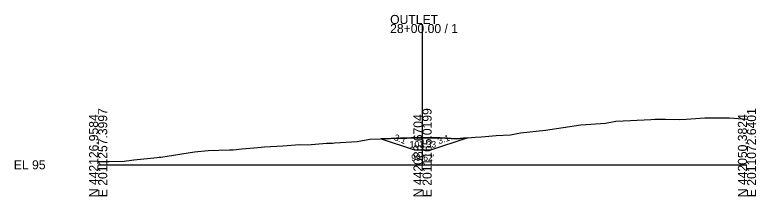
# Model space of a CAD drawing. Extents: x -26 to 1203, y -15 to 9526.
# Drawn here: x 974.3 to 1202.8, y 7990.3 to 8046.3 of the extents above; entities that cross this region are included whole.
import ezdxf

# ---------------------------------------------------------------- set-up
doc = ezdxf.new("R2010")
doc.units = 0
for name, color, linetype in [('Default', 7, 'Continuous'), ('Exist Cross Section Cell', 7, 'Continuous'), ('Exist XS Center Line Elevation Label', 7, 'Continuous'), ('Exist XS Ground Line', 7, 'Continuous'), ('Prop XS DDE', 7, 'Continuous'), ('Prop XS DDE Earthwork Shape', 7, 'Continuous'), ('Prop XS DDE Elevations', 7, 'Continuous'), ('Prop XS DDE Slope Text', 7, 'Continuous')]:
    doc.layers.add(name, color=color, linetype=linetype)

msp = doc.modelspace()

# ---------------------------------------------------------------- linework, layer by layer
at = {"layer": 'Exist Cross Section Cell'}
for p, q in [((1100, 8000), (1100, 8043.49)), ((1000, 8000), (1100, 8000)), ((1100, 8000), (1200, 8000))]:
    msp.add_line(p, q, dxfattribs=at)
at = {"layer": 'Exist XS Ground Line'}
msp.add_lwpolyline([(1000, 8001.01), (1003.34, 8001.04), (1008.01, 8001.1), (1010.99, 8001.53), (1018.17, 8002.27), (1018.83, 8002.35), (1019.3, 8002.41), (1029.66, 8003.97), (1033.95, 8004.44), (1040.48, 8004.66), (1041.6, 8004.65), (1044.29, 8004.95), (1049.25, 8005.39), (1051.31, 8005.59), (1056.91, 8005.9), (1062.13, 8006.23), (1064.56, 8006.18), (1070.41, 8006.71), (1072.21, 8006.73), (1072.96, 8006.77), (1079.87, 8007.24), (1083.78, 8007.91), (1093.25, 8008.27), (1094.61, 8008.28), (1095.17, 8008.26), (1096.53, 8008.36), (1100, 8008.33), (1105.43, 8008.29), (1110.48, 8008.07), (1116.26, 8008.58), (1118.13, 8008.61), (1122.65, 8009.09), (1127.08, 8009.31), (1130.23, 8009.89), (1137.91, 8010.69), (1148.76, 8012.37), (1156.4, 8012.91), (1159.56, 8013.45), (1164.05, 8013.69), (1170.38, 8014), (1171.7, 8014.09), (1174.88, 8014.09), (1179.35, 8013.96), (1181.21, 8014.11), (1187.01, 8014.49), (1192.03, 8014.46), (1194.66, 8014.5), (1200, 8014.06)], dxfattribs=at)
at = {"layer": 'Prop XS DDE'}
for p, q in [((1087.23, 8008.04), (1097.5, 8004.62)), ((1102.5, 8004.62), (1113.71, 8008.36)), ((1097.5, 8004.62), (1102.5, 8004.62))]:
    msp.add_line(p, q, dxfattribs=at)
at = {"layer": 'Prop XS DDE Earthwork Shape'}
msp.add_lwpolyline([(1087.23, 8008.04), (1097.5, 8004.62), (1102.5, 8004.62), (1113.71, 8008.36), (1110.48, 8008.07), (1105.43, 8008.29), (1100, 8008.33), (1096.53, 8008.36), (1095.17, 8008.26), (1094.61, 8008.28), (1093.25, 8008.27)], close=True, dxfattribs=at)

# ---------------------------------------------------------------- texts
at = {"layer": 'Default'}
msp.add_text("99.62'", height=2, dxfattribs=at).set_placement((1096.47, 8001.21))
at = {"layer": 'Exist Cross Section Cell'}
for s, p in [('OUTLET', (1090, 8043.49)), ('28+00.00 / 1', (1090, 8040.69)), ('EL 95', (974, 7998.6))]:
    msp.add_text(s, height=2.8, dxfattribs=at).set_placement(p)
for s, p in [('E 2011257.3997', (1002.8, 7990)), ('E 2011165.0199', (1102.8, 7990)), ('E 2011072.6401', (1202.8, 7990)), ('N 442126.9584', (1000, 7990)), ('N 442088.6704', (1100, 7990)), ('N 442050.3824', (1200, 7990))]:
    msp.add_text(s, height=2.8, rotation=90, dxfattribs=at).set_placement(p)
at = {"layer": 'Exist XS Center Line Elevation Label'}
msp.add_text('103.33', height=2, dxfattribs=at).set_placement((1095.99, 8005.33))
at = {"layer": 'Prop XS DDE Elevations'}
msp.add_text("99.62'", height=2, dxfattribs=at).set_placement((1096.47, 8001.21))
at = {"layer": 'Prop XS DDE Slope Text'}
for rotation, p in [(339.0265, (1091, 8007.69)), (19.4493, (1105.07, 8006.32))]:
    msp.add_text('3:1', height=2, rotation=rotation, dxfattribs=at).set_placement(p)

doc.saveas('drawing.dxf')
